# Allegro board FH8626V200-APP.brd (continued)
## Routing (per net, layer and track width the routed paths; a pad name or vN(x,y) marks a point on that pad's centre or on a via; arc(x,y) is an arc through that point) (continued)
D5.0V: length 218.3
  TOP w0.381: R10.1 119.76,48.26 v1(119.38,47.88) ; R7.1 v1(139.12,42.04) ; R91.2 v2(28.32,12.32)
  VCC w0.965: 44.09,6.4 28.63,6.4 26.16,3.94 21.59,3.94 20.32,5.21 20.32,20.32 12.83,27.81 10.41,27.81 4.57,33.66 4.57,53.95 5.54,54.91 8.97,54.91 9.96,55.91 v1(12.24,55.91) ; 44.09,6.4 57.66,6.4 60.08,8.83 80.51,8.83 84.25,5.08 91.06,5.08 92.49,3.65 94.2,3.65 95.61,5.05 103.23,5.05 108.36,10.19 119.87,10.19 122.05,12.36 122.05,28.07 ; 44.09,6.4 44.04,6.45 44.04,10.01
  VCC w1.016: 29.13,6.4 28.7,6.83 28.7,11.94 v2(28.32,12.32)
  BOTTOM w0.305: R105.1 43.81,11.05 43.99,11.23
  BOTTOM w0.381: v1(139.12,42.04) 139.24,41.91 R44.1 ; v1(121.41,33.15) 121.28,33.02 R18.1 ; R86.1 v1(121.28,29.46) ; R15.1 v1(121.18,36.2) ; R24.1 v1(118.49,45.44) ; R21.1 119.76,46.99 v1(119.38,47.37)
  vias: v1(11.68,55.88) v1(12.85,55.88) v1(43.84,11.43) v1(44.4,11.46) v1(102.49,71.5) v1(103,71.5) v1(103.5,71.5) v1(116.59,80.26) v1(117.09,80.26) v1(117.6,80.26) v1(118.87,47.88) v1(118.87,47.37) v1(121.41,32.64) v1(121.41,32.13) v1(121.41,26.54) v1(121.41,26.04) v1(121.41,25.53) v1(121.92,41.27) v1(121.92,40.77) v1(121.92,40.26) v1(121.92,33.15) v1(121.92,32.64) v1(121.92,32.13) v1(121.92,26.54) v1(121.92,26.04) v1(121.92,25.53) v1(122.43,41.27) v1(122.43,40.77) v1(122.43,40.26) v1(123.67,35) v1(123.67,34.44) v1(124.46,34.44) v1(125.17,35.1) v1(125.17,34.44) v1(128.07,42.04) v1(128.07,41.53) v1(128.07,41.02) v1(128.58,42.04) v1(128.58,41.53) v1(128.58,41.02)
D12V: length 8.4
  TOP w0.305: 133.1,23.75 v1(133.1,22.99)
  BOTTOM w0.305: R1.2 v1(133.1,13.59)
  BOTTOM w0.508: U19.1 C153.1 C152.1 v1(8.38,10.16)
  vias: v1(8.64,18.95) v1(8.66,18.41) v1(8.69,17.91) v1(9.25,18.97) v1(9.25,17.88) v1(9.27,18.44) v1(137.54,28.07) v1(140.13,28.27) v1(140.11,27.71) v1(140.13,27.18)
GND: length 2115.5
  TOP w0.102: v1(54.61,34.54) 54.61,33.48 53.37,32.23 v1(53.37,30.58) 53.37,28.42 v1(53.59,28.19) v1(53.59,25.4) ; v1(50.77,43.15) 45.16,43.15 v1(45.01,43) 44.96,42.95 v1(41.71,42.95) ; 64.49,23.77 64.52,23.75 v1(64.52,22.1) v1(64.52,21.21) 64.39,21.21 63.89,20.71 U7.2 63.46,20.4 62.87,19.81 60.71,19.81 60.2,20.32 v1(60.2,20.57) v1(60.2,21.46) v1(60.2,22.48) 60.2,23.62 v1(60.45,23.88) ; v1(60.86,31.83) 60.86,27.58 60.1,26.82 v1(60.1,24.89) ; v1(132.05,56.41) 129.44,53.8 v1(125.81,53.8) v1(121.77,53.8) v1(116.31,53.8) v1(110.67,53.8) v1(104.9,53.8) v1(101.63,53.8) 92.6,53.8 BT1.2 ; v1(54.56,35.51) 54.28,35.51 53.78,35.01 53.78,33.54 52.5,32.26 v1(52.5,31.5) v1(52.5,28.57) 52.5,25.07 v1(52.45,25.02) ; v1(52.83,48.72) 52.83,49.86 52.3,50.39 52.3,52.73 v1(51.63,53.4) 49.48,55.55 45.8,55.55 45.11,54.86 44.86,54.86 44.81,54.81 44.81,54.64 44.17,54 v1(43.66,54) v1(40.54,54) 40.46,54.08 37.85,54.08 37.67,54.25 37.67,56.57 v1(36.96,57.28) 36.96,57.43 37.19,57.66 38.25,57.66 38.48,57.43 v1(38.48,57.4) 38.48,56.06 38.73,55.8 v1(40.29,55.8) v1(44.6,55.8) 45.19,55.8 45.39,56.01 50.55,56.01 v1(50.79,55.77) v1(52.86,53.7) 53.21,53.34 v1(53.21,52.2) ; 43.99,50.72 43.99,52.83 46.15,54.99 48.77,54.99 51.05,52.7 v1(51.05,51.54) 51.05,50.44 51.7,49.8 v1(51.7,48.29) 51.7,47.38 53.44,45.64 v1(53.47,45.64) 53.47,45.62 54.15,44.94 54.39,44.94 54.53,44.8 54.53,44.6 54.51,44.58 58.06,41.02 ; v1(67.26,14.27) 62.92,14.27 v1(62.82,14.18) 62.17,14.83 v1(59.83,14.83) 58.37,14.83 v1(56.88,16.32) 54.56,18.64 v1(54.56,20.12) v1(54.56,22.91) v1(54.56,25.98) v1(54.56,28.5) v1(54.56,30.61) 54.56,32.46 v1(54.61,32.51) 54.99,32.89 55.37,32.89 55.75,32.51 55.75,31.98 56.03,31.7 v1(56.03,30.71) v1(56.03,27.74) v1(56.03,24.87) v1(56.03,23.09) v1(56.03,18.82) v1(57.18,17.68) 58.39,16.46 v1(60.81,16.46) v1(62.99,16.46) v1(66.95,16.46) 70.48,16.46 70.61,16.59 72.69,16.59 v1(73.08,16.21) v1(76.39,12.89) 76.81,12.47 79.48,12.47 v1(81.03,10.92) v1(83.4,8.55) 84.69,7.25 v1(87.02,7.25) U6.4 89.43,6.96 v1(94.08,6.96) 96.8,6.96 97.26,6.5 98.98,6.5 99.52,7.04 v1(99.52,8) 99.52,9.17 99.75,9.4 100.74,9.4 101.27,8.86 v1(101.27,7.75) 101.27,7.59 99.57,5.89 95.05,5.89 94.95,5.99 v1(91.41,5.99) v1(86.94,5.99) 84.58,5.99 v1(83.76,6.82) v1(79.77,10.81) 78.82,11.76 76.15,11.76 v1(75.18,12.73) 72.54,15.37 v1(71.7,15.37) 71.49,15.58 69.58,15.58 68.27,14.27 v1(67.26,14.27)
  TOP w0.178: v1(59.77,35.56) 59.65,35.68 U14.37
  TOP w0.254: U26.4 v1(108.75,79.33) ; v1(110.19,73.51) 110.05,73.64 U26.11 ; v1(110.87,79.38) 110.7,79.21 U26.1 ; C186.2 v1(111.63,71.88) ; C188.2 v1(124.97,71.88) ; v1(113.28,27.43) U12.2 v1(115.7,27.43)
  TOP w0.305: v1(14.22,23.5) 14.1,23.37 C87.2 ; R16.1 v1(117.47,37.59) ; T10.1 v1(100.84,44.83) ; v1(113.72,48.9) v1(113.21,48.9) v1(112.67,48.9) 111.2,48.9 111.18,48.92 111.15,48.9 C22.2 ; C65.1 v1(118.87,28.19) ; 134.37,23.75 v1(134.37,22.99) ; J3.30 v1(6.99,49.84) ; C6.2 v1(128.91,28.83) ; J3.37 v1(10.29,53.84) ; v1(64.57,48.31) 64.64,48.39 64.64,51.79 v1(65.18,52.32) v1(66.36,53.51) 68.92,56.07 69.53,56.07 70.18,56.72 v1(70.18,58.29) 70.18,59.23 69.6,59.82 v1(69.6,61.47) D24.K ; C72.1 v1(26.42,9.4) ; J3.38 v1(6.85,53.84) ; v1(106.55,32.61) 106.43,32.74 C29.2 ; v1(63.5,21.56) 63.46,21.52 U7.2 ; C78.1 v1(60.45,23.88) ; R88.1 v1(117.47,30.99) ; U27.4 v1(122.21,79.29) ; v1(132.51,40.26) v1(133.4,40.26) 133.53,40.39 v1(134.29,40.39) U2.2 136.45,40.39 ; U3.2 v1(115.95,48.9) ; J3.10 v1(6.99,39.84) ; C39.2 105.16,44.83 v1(104.9,45.09) ; J4.8 v1(40.26,61.09) ; C9.2 130.4,28.93 v1(130.3,28.83) ; v1(65.13,23.8) 65.1,23.77 64.49,23.77 C80.1 ; v1(60.78,47.83) v1(60.78,52.7) 60.78,55.52 59.56,56.74 v1(59.56,57) 59.77,57.2 59.77,59.16 60.2,59.59 v1(60.2,60.33) v1(60.2,61.44) D18.K ; C38.2 v1(106.55,45.59) ; U14.89 56.01,41.02 v1(55.75,41.27) ; v1(14.15,35.84) J3.1 ; D3.K v1(135.13,11.81) ; v1(60.2,22.48) 60.21,22.47 U7.4 ; C11.1 v1(130.23,40.01) ; C30.2 v1(104.9,33.27) ; C14.2 v1(129.34,42.47) ; C34.1 v1(120.9,43.56) ; C15.2 v1(130.86,42.52) ; v1(65.53,47.12) 65.56,47.14 v1(66.32,47.14) v1(67.16,47.14) 67.59,47.14 68.96,48.51 v1(70.48,48.51) v1(73.34,51.37) v1(75.37,53.4) v1(78.93,56.96) v1(83.38,61.4) v1(86.04,64.07) v1(87.45,65.48) 87.39,65.54 87.39,66.66 89.03,68.3 v1(89.03,71.5) D14.A ; C37.2 108.93,44.74 v1(108.97,44.7) ; v1(15.49,23.5) R104.2 ; v1(33.43,61.01) 33.56,60.88 J4.5 ; T2.1 v1(127.76,35.43) ; C35.1 v1(119.51,42.8) ; J3.18 v1(6.99,43.84) ; J3.24 v1(6.99,46.84) ; U27.11 v1(123.52,73.59) ; R9.1 v1(132.26,37.59) ; C67.2 v1(108.97,30.1) ; J3.26 v1(6.99,47.84) ; D21.K v1(63.25,61.39) v1(63.25,59.56) 63.25,59.31 63.93,58.62 v1(63.93,57.15) 63.93,56.26 63.25,55.58 63.25,55.4 62.71,54.86 v1(62.71,54.36) v1(62.71,52.96) ; v1(62,9.8) 62.53,9.27 C108.2 ; v1(62.71,52.96) v1(62.71,50.11) v1(62.71,48.92) ; v1(62.71,52.96) 63.42,52.96 64.38,53.91 v1(64.38,54.62) 65.89,56.13 v1(65.89,57.35) v1(65.89,59.84) 65.89,60.73 v1(66.55,61.39) D22.K ; J3.4 v1(6.99,36.84) ; C71.1 v1(26.54,11.43) ; C69.2 v1(104.9,30.86) ; U27.1 v1(124.17,79.33) ; C7.2 v1(127.51,29.34) ; C68.2 106.43,30.94 v1(106.55,31.06) ; 135.64,23.75 v1(135.64,22.99) ; C18.1 v1(116.71,49.66) ; J3.20 v1(6.99,44.84) ; C16.2 v1(127.94,43.05) ; 73.28,37.97 v1(73.91,37.97) ; C28.2 108.08,33.43 108.66,32.84 v1(108.66,32.54) ; v1(68.05,45.82) 68.3,45.82 69.34,46.86 v1(71.25,46.86) v1(74.04,49.66) v1(77.34,52.96) v1(81.22,56.83) v1(86.55,62.17) v1(89.31,64.92) v1(91.01,66.62) 92.2,67.82 v1(92.2,68.96) v1(92.2,69.9) v1(92.2,71.37) D13.K ; T18.1 v1(103.76,31.75) ; J3.6 v1(6.99,37.84) ; C12.1 v1(131.62,40.13) ; C40.2 v1(103.89,44.96) ; T5.1 v1(128.14,49.53) ; C17.1 v1(119.13,49.28) ; J3.12 v1(6.99,40.84) ; C26.1 v1(118.87,34.8) ; C79.1 v1(73.91,34.8) ; U9.4 v1(77.37,17.27) ; C21.2 v1(109.09,50.16) ; J21.4 v1(87.19,72.97) ; v1(120.27,28.7) C64.1 ; C25.1 v1(120.27,35.31) ; C19.2 v1(107.57,50.16) ; J3.32 v1(6.99,50.84)
  TOP w0.381: 13.54,22.61 C87.2 14.65,22.61 ; 50.16,3.09 CN1.5 ; CN1.5 51.44,4.36 ; CN1.5 51.44,1.82 ; CN1.5 52.71,3.09 ; 48.34,80.49 J4.15 ; J4.15 47.24,81.97 ; J4.15 48.34,83.46 ; J4.15 49.43,81.97 ; 79.18,17.74 U9.4 79.18,16.8 ; S1.1 127.25,12.06 ; S1.1 124.71,12.06 ; S1.1 125.98,13.34 ; S1.1 125.98,10.79 ; 25.21,10.79 C71.1 ; C71.1 25.91,11.46 ; C71.1 25.91,10.13 ; C71.1 26.61,10.79 ; J13.CG1 5.29,66.98 ; J13.CG1 3.73,65.77 ; J13.CG1 3.73,68.19 ; J13.CG1 2.17,66.98 ; 16.46,2.96 J7.CG2 ; J7.CG2 15.25,4.52 ; J7.CG2 17.67,4.52 ; J7.CG2 16.46,6.09 ; 120.06,42.16 C35.1 118.95,42.16 ; U18.16 153.8,57.91 ; U18.16 151.76,57.91 ; U18.16 152.78,58.93 ; 64.39,23.32 C80.1 ; C80.1 64.94,23.88 ; C80.1 64.39,24.43 ; J7.CG1 11.42,4.52 ; J7.CG1 10.21,2.96 ; J7.CG1 9,4.52 ; J7.CG1 10.21,6.09 ; J19.CG2 115.56,86.95 ; J19.CG2 114.36,85.38 ; J19.CG2 114.36,88.51 ; J19.CG2 113.15,86.95 ; JP6.2 4.62,79.59 ; JP6.2 2.59,79.59 ; JP6.2 3.6,80.6 ; JP6.2 3.6,78.57 ; 4.96,43.27 J3.18 3.52,43.84 ; 92.58,13.49 U6.9 ; U6.9 94.11,13.49 ; U6.9 93.34,12.73 ; 137.54,55.37 JP5.2 ; JP5.2 139.57,55.37 ; JP5.2 138.56,56.39 ; JP5.2 138.56,54.36 ; 17.63,18.8 U16.2 16.11,18.8 ; J15.CG2 6.09,10.46 ; J15.CG2 4.52,9.26 ; J15.CG2 4.52,11.67 ; J15.CG2 2.96,10.46 ; 59.63,62.1 D18.K 60.2,62.61 ; 60.2,4.68 J6.2 ; J6.2 61.21,5.7 ; J6.2 62.23,4.68 ; J6.2 61.21,3.67 ; 88.45,72.26 D14.A 89.03,72.77 ; 117.22,2.92 117.22,3.94 ; 117.22,2.92 118.24,2.92 ; 117.22,2.92 116.2,2.92 ; 73.28,34.24 C79.1 72.72,34.8 ; BT1.2 89.53,53.53 ; BT1.2 89.53,47.94 ; BT1.2 87.88,50.73 ; BT1.2 91.19,50.73 ; 119.61,34.42 C25.1 120.93,34.42 ; U18.18 152.78,56.39 ; U18.18 153.8,55.37 ; U18.18 152.78,54.36 ; U18.18 151.76,55.37 ; 126.36,35.43 T2.1 127,36.07 ; 16.11,19.75 U16.3 ; U16.3 16.87,20.23 ; U16.3 17.63,19.75 ; 129.05,2.97 J12.2 129.05,4.39 ; U18.8 152.78,69.09 ; U18.8 152.78,67.06 ; U18.8 153.8,68.07 ; JP5.1 139.57,52.83 ; JP5.1 138.56,53.85 ; JP5.1 137.54,52.83 ; JP5.1 138.56,51.82 ; U18.6 153.8,70.61 ; U18.6 152.78,69.6 ; U18.6 151.76,70.61 ; R5.1 130.81,28 ; R5.1 130.3,27.43 ; R5.1 131.32,27.43 ; 100.96,50.67 T6.1 ; T6.1 v1(102.36,50.67) ; T6.1 101.6,51.31 ; T6.1 101.6,50.04 ; J20.CG2 126.93,88.51 ; J20.CG2 128.14,86.95 ; J20.CG2 125.72,86.95 ; J20.CG2 126.93,85.38 ; 65.98,62.1 D22.K 66.55,62.61 ; 3.73,72.02 J13.CG2 ; J13.CG2 5.29,73.23 ; J13.CG2 3.73,74.44 ; J13.CG2 2.17,73.23 ; 63.25,62.61 D21.K 63.82,62.1 ; 5.46,71.29 J13.2 6.88,70.73 ; J17.13 56.99,82.61 ; J17.13 55.55,81.18 ; J17.13 56.99,79.74 ; J17.13 58.43,81.18 ; JP6.1 4.62,77.05 ; JP6.1 3.6,78.06 ; JP6.1 3.6,76.03 ; JP6.1 2.59,77.05 ; 73.25,79.74 J17.14 ; J17.14 71.81,81.18 ; J17.14 74.69,81.18 ; J17.14 73.25,82.61 ; C5.2 139.93,25.78 ; C5.2 138.97,24.89 ; C5.2 138.02,25.78 ; C4.2 142.31,25.78 ; C4.2 140.41,25.78 ; C4.2 141.36,24.89 ; 113.69,34.04 U4.2 115.52,34.04 ; U18.12 152.78,64.01 ; U18.12 153.8,62.99 ; U18.12 152.78,61.98 ; U18.12 151.76,62.99 ; J20.CG1 119.39,86.95 ; J20.CG1 118.18,85.38 ; J20.CG1 116.97,86.95 ; J20.CG1 118.18,88.51 ; 81.48,78.77 J21.CG2 ; J21.CG2 84.66,78.77 ; J21.CG2 83.07,81.48 ; J21.CG2 83.07,76.07 ; 137.16,25.73 C2.2 137.71,26.29 ; 116.15,42.16 U5.2 114.32,42.16 ; 4.52,15.51 J15.CG1 ; J15.CG1 2.96,16.71 ; J15.CG1 6.09,16.71 ; J15.CG1 4.52,17.92 ; 127,48.89 T5.1 ; T5.1 127,50.17 ; T5.1 126.36,49.53 ; 110.49,51.18 110.49,51.74 ; 110.49,51.18 111.04,51.18 ; 110.49,51.18 109.94,51.18 ; 130.2,43.31 C15.2 131.52,43.31 ; 9.33,21.15 C105.2 ; C105.2 10.29,22.04 ; C105.2 11.24,21.15 ; 130.48,37.59 R9.1 130.99,37.02 ; 153.92,11.45 C3.2 ; C3.2 154.94,12.47 ; C3.2 152.91,12.47 ; C3.2 153.92,13.49 ; 117.27,48.9 C18.1 116.16,48.9 ; 134.87,23.75 133.86,23.75 ; 116.71,38.16 R16.1 116.2,37.59 ; C23.1 v1(115.82,51.56) ; 142.62,6.89 J1.2 ; J1.2 144.53,7.84 ; J1.2 140.72,7.84 ; J1.2 142.62,8.8 ; S2.1 125.98,22.23 ; S2.1 124.71,20.95 ; S2.1 127.25,20.95 ; S2.1 125.98,19.68 ; 129.57,29.72 C6.2 128.24,29.72 ; 123.65,71.88 C188.2 124.21,71.33 ; J21.CG1 98.32,81.48 ; J21.CG1 99.91,78.77 ; J21.CG1 98.32,76.07 ; J21.CG1 96.73,78.77 ; v1(13.84,38.84) J3.7 ; T18.1 104.39,30.99 ; T18.1 103.76,30.35 ; T18.1 103.12,30.99 ; 11.56,19.81 C106.2 ; C106.2 12.06,20.32 ; C106.2 12.57,19.81 ; 11.18,85.41 J14.3 ; J14.3 12.26,86.49 ; J14.3 10.1,86.49 ; J14.3 11.18,87.57 ; U18.10 152.78,66.55 ; U18.10 152.78,64.52 ; U18.10 153.8,65.53 ; 92.77,72.26 D13.K 92.2,72.77 ; 146.47,11.34 J1.3 ; J1.3 148.37,11.34 ; J1.3 147.42,9.44 ; J1.3 147.42,13.25 ; 119.61,27.81 C64.1 120.93,27.81 ; J21.4 87.19,77.01 ; J21.4 88.02,75.31 ; J21.4 86.37,75.31 ; C28.2 108.74,33.53 ; C28.2 107.42,33.53 ; C28.2 108.08,34.23 ; 138.41,16.83 D2.A ; D2.A 137.31,18.29 ; D2.A 138.41,19.75 ; 138.36,38.94 C20.1 ; C20.1 v1(139.12,39.5) ; C20.1 138.36,40.05 ; U15.4 118.24,5.46 ; U15.4 116.2,5.46 ; U15.4 117.22,4.44 ; U15.4 117.22,6.48 ; 18.94,81.97 J4.16 ; J4.16 20.04,80.49 ; J4.16 21.13,81.97 ; J4.16 20.04,83.46 ; 130.43,40.13 C12.1 130.99,39.58 ; 120.24,42.55 C34.1 121.57,42.55 ; 105.61,85.38 J19.CG1 ; J19.CG1 106.81,86.95 ; J19.CG1 104.4,86.95 ; J19.CG1 105.61,88.51 ; v1(13.84,48.51) 13.51,48.84 J3.27 ; 58.42,37.71 U14.89 ; U14.89 61.74,41.02 ; U14.89 58.42,44.34 ; T8.1 104.27,36.83 ; T8.1 103,36.83 ; T8.1 103.63,37.47 ; 25.92,4.52 J5.CG2 ; J5.CG2 27.13,2.96 ; J5.CG2 28.33,4.52 ; J5.CG2 27.13,6.09 ; 151.51,38.6 J2.3 ; J2.3 148.08,39.99 ; J2.3 151.51,41.39 ; J2.3 154.94,39.99 ; 61.21,24.43 C78.1 61.21,23.32 ; 29.78,20.45 30.86,20.45 ; 30.86,20.45 30.86,19.37 ; 30.86,20.45 31.94,20.45 ; 30.86,20.45 30.86,21.53 ; U6.10 94.11,4.79 ; U6.10 92.58,4.79 ; U6.10 93.34,4.03 ; R8.1 138.36,41.28 ; R8.1 138.36,40.26 ; R8.1 v1(139.12,40.77) ; 110.32,71.88 C186.2 110.87,71.33 ; 129.34,39.31 C11.1 128.68,40.01 ; 151.76,60.45 U18.14 ; U18.14 152.78,59.44 ; U18.14 152.78,61.47 ; U18.14 153.8,60.45 ; 16,22.61 R104.2 14.99,22.61 ; v1(13.97,41.84) J3.13 ; J3.13 10.58,41.84 ; J3.13 12.02,42.41 ; 106.91,49.28 C19.2 108.23,49.28 ; 39.45,59.77 J4.8 41.06,59.77 ; 61.26,21.7 U7.4 61.26,23.23 ; 25.4,8.84 C72.1 25.4,9.95 ; U18.20 153.8,52.83 ; U18.20 151.76,52.83 ; U18.20 152.78,53.85 ; U18.20 152.78,51.82 ; 133.73,27.3 U1.2 131.95,27.3 ; CN5.5 35.56,4.36 ; CN5.5 34.29,3.09 ; CN5.5 35.56,1.82 ; CN5.5 36.83,3.09 ; U18.4 153.8,73.15 ; U18.4 151.76,73.15 ; U18.4 152.78,74.17 ; T10.1 101.73,45.47 ; T10.1 102.36,44.83 ; T10.1 101.73,44.2 ; C29.2 107.09,33.53 ; C29.2 105.76,33.53 ; C29.2 106.43,34.23 ; R11.1 v1(117.22,51.56) ; 136.19,23.75 135.08,23.75 ; 105.71,44.32 C39.2 104.6,44.32 ; 131.06,29.75 C9.2 129.74,29.75 ; 130,43.31 C14.2 128.68,43.31 ; 104.35,29.97 C69.2 105.46,29.97 ; v1(13.84,45.84) J3.21 ; D3.K 135.79,12.96 ; D3.K 134.47,12.96 ; D3.K 135.13,13.62 ; 20.88,2.96 J5.CG1 ; J5.CG1 22.09,4.52 ; J5.CG1 19.67,4.52 ; J5.CG1 20.88,6.09 ; 12.02,35.27 J3.1 10.58,35.84 ; 103.33,44.32 C40.2 104.44,44.32 ; 119.43,34.04 C26.1 118.32,34.04 ; 119.43,27.43 C65.1 118.32,27.43 ; 116.33,45.59 R26.1 ; R26.1 117.22,45.59 v1(117.47,45.34) ; R26.1 116.84,46.17 ; 110.49,49.45 C22.2 109.94,48.9 ; 109.75,49.28 C21.2 108.43,49.28 ; J3.33 14.86,51.84 ; 70.17,62.1 D24.K 69.6,62.61
  TOP w0.508: J13.2 v1(3.69,70.73)
  VCC w0.102: v1(65.43,27.99) 67.31,26.11 89.46,26.11 90.17,26.82 90.17,28.7 89.76,29.11 v1(89.36,29.11) ; 65.43,22.76 v1(67.36,22.76) v1(68.66,22.76) v1(71.15,22.76) v1(74.07,22.76) v1(77.19,22.76) v1(81.79,22.76) 83.08,21.46 90.6,21.46 91.9,22.76 v1(93.4,22.76) ; 65.43,22.76 v1(65.33,22.76) 64.87,22.76 61.59,26.04 54.61,26.04 v1(54.56,25.98) 54.91,25.98 v1(56.03,24.87) ; 65.43,22.76 65.43,22.48 66.19,21.72 v1(70.87,21.72) 71.02,21.87 78.61,21.87 78.69,21.79 v1(79.15,21.79) 79.15,21.46 78.54,20.85 v1(72.14,20.85) v1(67.82,20.85) 64.92,20.85 ; 33.9,55.77 27.17,55.77 v1(26.8,56.13) 26.47,56.13 26.09,55.75 24.77,55.75 22.81,57.71 v1(22.81,59.03) ; 33.9,55.77 40.25,55.77 ; 33.9,55.77 v1(33.53,56.13) ; 40.25,55.77 44.56,55.77 v1(44.6,55.8) 45.54,56.74 49.81,56.74 v1(50.79,55.77) 53.1,55.77 57.07,51.79 58.29,51.79 58.45,51.94 59.49,51.94 59.72,51.71 59.99,51.71 ; 40.25,55.77 v1(40.29,55.8) ; v1(43.66,54) 45.03,54 46.01,54.98 48.65,54.98 51.05,52.57 v1(51.05,51.54) ; v1(63.5,21.56) 64.21,20.85 64.92,20.85 ; v1(55.91,34.95) 56.72,35.76 57.15,35.76 57.28,35.89 59.44,35.89 v1(59.77,35.56) 60.05,35.84 61.14,35.84 61.2,35.78 ; 64.92,20.85 v1(64.52,20.45) 64.39,20.32 60.45,20.32 v1(60.2,20.57) 58.55,20.57 v1(56.03,23.09) 53.98,25.15 53.85,25.15 v1(53.59,25.4) 53.47,25.53 52.96,25.53 v1(52.45,25.02) 52.45,24.89 54.43,22.91 v1(54.56,22.91) 54.81,22.91 v1(56.05,21.68) 57.89,19.84 v1(57.96,19.84) 58.09,19.84 58.32,19.61 65.96,19.61 v1(66.17,19.81) v1(68.78,19.81) v1(90.5,19.81) 92.99,19.81 v1(93.34,19.46) ; v1(87.86,23.83) v1(83.59,23.83) v1(78.36,23.83) v1(73.79,23.83) v1(69.27,23.83) 65.02,23.83 61.11,27.74 v1(56.03,27.74) 55.97,27.8 55.26,27.8 v1(54.56,28.5) ; v1(80.16,20.85) 80.26,20.75 91.62,20.75 v1(91.95,21.08) 95.22,21.08 v1(96.58,19.72) 97.87,18.44 v1(100.79,18.44) ; v1(74.8,46.23) 74.4,45.82 v1(68.05,45.82) 67.74,45.82 67.59,45.97 v1(64.39,45.97) ; v1(65.71,30.1) 65.71,29.51 68.2,27.03 71.37,27.03 72.19,27.84 v1(72.72,27.84)
  VCC w0.381: C3.2 154.94,12.47 ; C3.2 153.92,13.49 ; C3.2 152.91,12.47 ; C3.2 153.92,11.45 ; 152.78,67.06 U18.8 ; U18.8 151.76,68.07 ; U18.8 152.78,69.09 ; U18.8 153.8,68.07 ; U6.10 93.34,5.56 ; U6.10 94.11,4.79 ; U6.10 92.58,4.79 ; J2.3 151.51,41.39 ; J2.3 151.51,38.6 ; J2.3 148.08,39.99 ; J2.3 154.94,39.99 ; U18.12 153.8,62.99 ; U18.12 152.78,61.98 ; U18.12 152.78,64.01 ; U18.12 151.76,62.99 ; 124.71,20.95 S2.1 ; S2.1 127.25,20.95 ; S2.1 125.98,19.68 ; S2.1 125.98,22.23 ; 151.76,65.53 U18.10 ; U18.10 152.78,66.55 ; U18.10 153.8,65.53 ; U18.10 152.78,64.52 ; 152.78,54.36 U18.18 ; U18.18 151.76,55.37 ; U18.18 153.8,55.37 ; U18.18 152.78,56.39 ; 3.6,76.03 JP6.1 ; JP6.1 3.6,78.06 ; JP6.1 4.62,77.05 ; JP6.1 2.59,77.05 ; U6.9 94.11,13.49 ; U6.9 92.58,13.49 ; U6.9 93.34,14.26 ; U6.9 93.34,12.73 ; 152.78,51.82 U18.20 ; U18.20 151.76,52.83 ; U18.20 152.78,53.85 ; U18.20 153.8,52.83 ; 152.78,72.14 U18.4 ; U18.4 151.76,73.15 ; U18.4 152.78,74.17 ; U18.4 153.8,73.15 ; 138.56,51.82 JP5.1 ; JP5.1 139.57,52.83 ; JP5.1 138.56,53.85 ; JP5.1 137.54,52.83 ; 35.56,1.82 CN5.5 ; CN5.5 36.83,3.09 ; CN5.5 34.29,3.09 ; J17.14 73.25,82.61 ; J17.14 71.81,81.18 ; J17.14 74.69,81.18 ; J17.14 73.25,79.74 ; U18.16 153.8,57.91 ; U18.16 152.78,58.93 ; U18.16 151.76,57.91 ; U18.16 152.78,56.9 ; U18.14 153.8,60.45 ; U18.14 152.78,59.44 ; U18.14 152.78,61.47 ; U18.14 151.76,60.45 ; 11.18,85.41 J14.3 ; J14.3 12.26,86.49 ; J14.3 10.1,86.49 ; J14.3 11.18,87.57 ; JP6.2 3.6,80.6 ; JP6.2 2.59,79.59 ; JP6.2 3.6,78.57 ; JP6.2 4.62,79.59 ; U18.6 153.8,70.61 ; U18.6 151.76,70.61 ; U18.6 152.78,71.63 ; U18.6 152.78,69.6 ; 29.78,20.45 30.86,20.45 ; 30.86,20.45 30.86,19.37 ; 30.86,20.45 30.86,21.53 ; 30.86,20.45 31.94,20.45 ; U6.4 89.9,7.25 ; U6.4 88.37,7.25 ; U6.4 89.13,8.02 ; U6.4 89.13,6.49 ; 50.16,3.09 CN1.5 ; CN1.5 52.71,3.09 ; CN1.5 51.44,1.82 ; 138.56,54.36 JP5.2 139.57,55.37 ; J1.3 148.37,11.34 ; J1.3 147.42,9.44 ; J1.3 147.42,13.25 ; J1.3 146.47,11.34 ; 55.55,81.18 J17.13 ; J17.13 56.99,82.61 ; J17.13 58.43,81.18 ; J17.13 56.99,79.74 ; 116.2,5.46 U15.4 118.24,5.46 ; 117.22,2.92 118.24,2.92 ; 117.22,2.92 117.22,1.9 ; 117.22,2.92 116.2,2.92 ; 61.21,3.67 J6.2 62.23,4.68 ; S1.1 127.25,12.06 ; S1.1 125.98,13.34 ; S1.1 124.71,12.06 ; J1.2 144.53,7.84 ; J1.2 142.62,6.89 ; J1.2 142.62,8.8 ; J1.2 140.72,7.84
  BOTTOM w0.102: 36.91,41.66 v1(36.4,41.15) v1(33.81,38.56) 31.13,35.88 v1(30.76,35.88) v1(25.17,35.88) v1(21.51,35.88) 21.48,35.84 v1(14.15,35.84) 14.08,35.84 v1(8.26,41.66) 7.65,42.27 7.25,42.27 6.99,42.01 v1(6.99,40.84) v1(9.63,38.2) 13.25,34.57 v1(14.38,34.57) v1(18.62,34.57) v1(20.93,34.57) v1(23.34,34.57) v1(27.61,34.57) 32.08,34.57 v1(32.28,34.77) v1(36.39,38.87) 38.02,40.51 v1(43,40.51) 43.13,40.64 v1(46.63,40.64) ; 36.91,41.66 v1(38.2,42.95) v1(39.83,44.58) v1(41.66,44.58) ; 36.91,41.66 v1(40.41,41.66) 41.66,41.66 ; v1(50.04,36.7) 49.91,36.7 49.53,36.32 48.64,36.32 48.26,35.94 48.26,35.81 48.13,35.69 46.23,35.69 45.85,35.31 v1(45.72,35.31) 45.72,35.18 42.42,31.88 v1(42.42,30.23) 42.42,26.16 v1(43.81,24.77) v1(46.67,21.91) v1(48.77,19.81) v1(51.56,17.02) 52.37,16.21 52.37,15.85 52.49,15.74 52.72,15.74 52.96,15.49 v1(54.74,15.49) ; 40.64,26.16 v1(40.64,28.32) 40.64,32.26 v1(40.77,32.38) 40.77,32.64 v1(42.93,34.8) 45.21,37.08 v1(47.24,37.08) ; 40.64,26.16 v1(44.26,22.54) v1(47.31,19.49) v1(49.66,17.14) v1(51.31,15.49) ; 40.64,26.16 v1(40.64,22.48) v1(40.64,20.07) 37.72,17.14 v1(37.72,14.73) ; 41.66,41.66 41.66,42.9 v1(41.71,42.95) 41.66,43 v1(41.66,44.58) ; 41.66,41.66 v1(45.97,41.66) ; v1(6.85,53.84) 8.13,53.84 13.46,48.51 v1(13.84,48.51) v1(16.64,48.51) v1(24.51,48.51) v1(31.67,48.51) v1(39.12,48.51) 42.04,48.51 v1(45.97,44.58) ; v1(51.7,48.29) 51.42,48.01 48.74,48.01 v1(48.46,48.29) ; v1(48.13,34.54) 47.24,34.54 v1(45.85,33.15) 43.94,31.24 v1(43.94,30.1) 43.94,27.51 v1(43.94,27.51) 43.94,27.06 v1(46.23,24.77) v1(48.77,22.23) v1(51.05,19.94) v1(52.83,18.16) 56.64,18.16 57.78,17.02 v1(57.78,13.34) ; v1(41.66,44.58) v1(41.66,45.97) 41.66,46.7 41.01,47.35 39.17,47.35 39.12,47.29 ; v1(19.79,38.89) 13.89,38.89 v1(13.84,38.84) ; 25.45,38.89 v1(26.87,38.89) v1(30.94,38.89) 31.57,38.89 v1(34.51,41.82) v1(37.36,44.68) v1(38.79,46.1) 39.12,46.43 v1(39.12,46.86) 39.12,47.29 ; 39.12,47.29 38.96,47.14 v1(37.26,47.14) 36.86,47.14 36.41,46.7 v1(34.71,46.7) v1(31.37,46.7) v1(28.38,46.7) v1(23.77,46.7) 16.76,46.7 v1(15.9,45.84) v1(13.84,45.84) ; v1(10.29,53.84) 14.6,49.53 v1(15.49,49.53) v1(22.61,49.53) v1(29.84,49.53) v1(38.1,49.53) 42.16,49.53 45.85,45.85 48.51,45.85 C52.1 ; 48.01,37.08 C55.2 48.01,37.47 48.39,37.85 49.82,37.85 50.29,38.33 50.29,38.86 50.04,39.12 v1(49.91,39.12) 49.89,39.09 49.63,39.09 49.53,38.99 47.37,38.99 v1(46.74,38.35) 44.32,38.35 v1(43.75,37.78) v1(41.78,35.81) v1(40.13,34.16) 38.18,32.21 v1(38.18,28.96) v1(38.18,24.74) v1(38.18,21.97) 38.18,20.65 35.81,18.29 34.77,18.29 v1(33.76,17.27) ; v1(21.21,41.22) v1(18.06,41.22) v1(15.54,41.22) 14.66,41.22 14.3,41.58 14.23,41.58 v1(13.97,41.84)
  BOTTOM w0.178: R31.2 v1(64.39,45.97) ; C57.2 55.93,34.42 v1(55.91,34.44)
  BOTTOM w0.201: C75.2 C74.2 51.31,40.01 50.84,40.48 v1(50.52,40.48)
  BOTTOM w0.305: C163.2 v1(115.32,21.59) ; C161.2 v1(107.19,14.22) ; C52.1 49.38,45.34 49.68,45.03 v1(49.68,44.75) ; C158.2 v1(98.17,72.77) ; R46.2 v1(26.8,56.13) ; Q1.2 v1(47.17,70) ; C100.1 67.18,12.32 v1(66.8,12.7) ; v1(68.07,42.8) 67.94,42.67 C49.2 C51.2 65.66,42.67 v1(65.53,42.8) ; R87.1 114.96,29.46 v1(114.83,29.34) ; C102.2 v1(79.76,34.04) ; v1(99.82,72.39) 99.69,72.52 C159.2 ; C195.1 v1(123.83,4.83) ; C62.2 v1(140.51,43.18) R84.2 ; C147.2 v1(30.73,13.59) ; v1(114.68,20.22) 115.09,19.81 C164.2 ; C116.2 C117.2 56.21,36.62 56.21,37.33 56.21,37.34 v1(56.21,37.36) ; R43.2 v1(18.16,57.02) ; C44.2 50.55,44.96 50.34,44.75 v1(50.19,44.75) ; C135.2 v1(48.13,34.54) ; v1(110.36,18.03) 110.24,18.16 C162.2 ; v1(53.21,52.2) 53.34,52.2 53.47,52.07 C178.2 ; R142.2 v1(145.16,55.37) ; C107.1 v1(41.78,12.45) R106.1 ; v1(60.96,33.27) 60.71,33.53 C121.2 ; v1(59.94,62.87) 60.71,63.63 C165.2 ; v1(55.12,44.7) 56.26,45.85 57.28,45.85 ; RF2.1 v1(34.42,12.95) ; v1(35.26,62.38) 35.53,62.1 C103.2 ; C124.2 v1(59.18,48.9) C125.2 ; C177.2 56.01,30.73 v1(56.03,30.71) ; R48.2 v1(33.53,56.13) ; C167.2 69.09,63.63 v1(69.85,62.87) ; 59.31,77.34 v1(59.94,77.34) ; C43.2 C42.2 66.17,46.99 v1(66.32,47.14) ; C43.2 67.31,46.99 v1(67.16,47.14) ; C43.2 67.89,45.97 v1(68.05,45.82) ; 61.85,77.34 v1(61.85,78.36) ; C119.2 v1(45.72,9.91) ; v1(56.52,42.74) 56.45,42.67 55.12,42.67 ; Q3.2 v1(7.29,75.24) ; v1(60.91,34.32) 60.81,34.42 C120.2 ; C45.1 62.61,34.01 v1(63.07,34.47) 62.61,34.92 C50.1 ; D19.A v1(73.79,77.34) ; v1(60.13,32.91) 60.11,32.93 59.93,32.93 59.88,32.98 58.97,32.98 58.66,33.29 C98.2 C58.2 ; C148.2 v1(131.19,5.84) D8.K ; R80.2 v1(46.86,70.74) ; U10.4 v1(77.57,13.46) ; C122.2 62.48,48.69 v1(62.71,48.92) ; D10.A v1(128.65,4.57) ; C194.2 v1(123.83,3.43) ; v1(113.31,34.37) v1(113.31,33.81) 114.05,33.07 C32.2 ; 47.88,40.51 v1(49.78,40.51) ; C114.2 v1(49.58,34.54) ; v1(62.71,50.11) 62.48,49.89 C123.2 ; v1(42.55,14.61) U11.2 v1(42.55,17.02) v1(42.55,17.78) v1(42.55,18.67) ; 48.01,37.08 v1(47.24,37.08) ; Q4.2 v1(102.44,69.27) ; C113.2 v1(54.86,16.26) ; R139.2 v1(145.03,62.99) ; C60.2 v1(103.38,10.54) ; C160.2 v1(111.12,14.22) ; R176.1 v1(67.94,77.34) ; C70.1 v1(113.51,29.46) ; R173.1 v1(113.54,14.22) ; D9.A v1(125.35,4.57)
  BOTTOM w0.381: 93.34,4.03 U6.10 ; U6.10 93.34,5.56 ; U6.10 94.11,4.79 ; U6.10 92.58,4.79 ; C184.1 110.49,74.85 ; C184.1 111.04,74.3 ; C184.1 110.49,73.74 ; 152.78,72.14 U18.4 ; U18.4 153.8,73.15 ; U18.4 151.76,73.15 ; U18.4 152.78,74.17 ; J2.3 151.51,41.39 ; J2.3 154.94,39.99 ; J2.3 148.08,39.99 ; J2.3 151.51,38.6 ; 152.78,59.44 U18.14 ; U18.14 151.76,60.45 ; U18.14 153.8,60.45 ; U18.14 152.78,61.47 ; 25.65,56.13 R46.2 26.16,56.71 ; 41.15,12.95 R106.1 41.15,11.94 ; 145.8,75.61 C150.1 145.24,75.06 ; 152.78,69.6 U18.6 ; U18.6 153.8,70.61 ; U18.6 151.76,70.61 ; U18.6 152.78,71.63 ; 57.78,45.85 57.28,45.85 57.28,45.34 ; JP6.2 4.62,79.59 ; JP6.2 3.6,80.6 ; JP6.2 3.6,78.57 ; JP6.2 2.59,79.59 ; 114.68,33.02 R19.2 ; R19.2 115.19,33.59 ; R19.2 115.7,33.02 ; v1(55.9,33.4) 55.9,33.4 C48.2 ; D25.A 27.6,5.84 ; D25.A 26.18,5.84 ; D25.A v1(26.89,6.82) ; D25.A 26.89,5.1 ; 47.83,69.22 Q1.2 46.51,69.22 ; J1.3 147.42,13.25 ; J1.3 148.37,11.34 ; J1.3 146.47,11.34 ; J1.3 147.42,9.44 ; 141.78,43.18 R84.2 141.28,42.61 ; U10.9 77.38,15.37 ; U10.9 75.43,12.95 ; U10.9 75.43,17.78 ; 46.74,16.13 46.74,16.83 ; 46.74,16.13 46.07,16.13 ; 46.74,16.13 46.74,15.43 ; 46.74,16.13 47.4,16.13 ; 88.37,7.25 U6.4 ; U6.4 89.13,6.49 ; U6.4 89.9,7.25 ; U6.4 89.13,8.02 ; D16.A 73.81,72.71 ; D16.A 73.81,69.79 ; D16.A 74.91,71.25 ; 114.05,14.99 R173.1 113.03,14.99 ; 114.93,36.2 R17.1 ; R17.1 115.44,36.77 ; R17.1 115.95,36.2 ; v1(51.69,37.21) 51.56,37.08 C63.1 ; CN1.5 51.44,4.36 ; CN1.5 51.44,1.82 ; CN1.5 52.71,3.09 ; CN1.5 50.16,3.09 ; J17.13 56.99,82.61 ; J17.13 58.43,81.18 ; J17.13 55.55,81.18 ; J17.13 56.99,79.74 ; 68.71,77.85 R176.1 68.71,76.83 ; U18.18 152.78,56.39 ; U18.18 152.78,54.36 ; U18.18 153.8,55.37 ; U18.18 151.76,55.37 ; J6.2 61.21,5.7 ; J6.2 62.23,4.68 ; J6.2 61.21,3.67 ; J6.2 60.2,4.68 ; 152.78,64.52 U18.10 ; U18.10 152.78,66.55 ; U18.10 153.8,65.53 ; U18.10 151.76,65.53 ; 131.75,5.21 C148.2 131.19,4.65 ; 125.98,19.68 S2.1 ; S2.1 127.25,20.95 ; S2.1 125.98,22.23 ; S2.1 124.71,20.95 ; C91.2 60.96,39.67 ; C91.2 60.52,39.12 v1(60.33,38.93) ; C91.2 61.51,39.12 ; 22.59,9.35 U13.7 ; U13.7 23.11,10.5 ; U13.7 23.64,9.35 ; C83.1 55.67,37.34 ; C83.1 55.12,36.78 ; C83.1 55.12,37.89 ; 46.35,71.5 R80.2 47.37,71.5 ; 61.47,45.72 R49.2 ; R49.2 61.47,46.74 ; R49.2 62.81,46.23 v1(63.37,46.79) ; 113.49,33.02 C32.2 114.6,33.02 ; 124.71,12.06 S1.1 ; S1.1 127.25,12.06 ; S1.1 125.98,13.34 ; S1.1 125.98,10.79 ; 152.78,61.98 U18.12 ; U18.12 151.76,62.99 ; U18.12 152.78,64.01 ; U18.12 153.8,62.99 ; C31.1 114.17,36.75 ; C31.1 114.73,36.2 ; C31.1 113.62,36.2 ; U18.8 152.78,69.09 ; U18.8 151.76,68.07 ; U18.8 153.8,68.07 ; U18.8 152.78,67.06 ; 114.73,29.46 C70.1 114.17,30.02 ; C183.1 124.51,74.3 ; C183.1 123.95,73.74 ; C183.1 123.95,74.85 ; 111,72.11 C185.1 ; C185.1 111,73.43 ; C185.1 110.3,72.77 ; C185.1 111.7,72.77 ; 25.4,17.83 C59.1 25.95,17.27 ; 45.72,11.22 C119.2 45.17,10.67 ; 48.9,33.99 C135.2 49.45,34.54 ; U6.9 94.11,13.49 ; U6.9 92.58,13.49 ; U6.9 93.34,14.26 ; U6.9 93.34,12.73 ; 129.22,5.21 D10.A 128.65,5.72 ; C149.2 13.72,69.64 ; C149.2 14.27,69.09 ; C149.2 v1(13.72,68.45) ; 56.12,69.79 D15.A ; D15.A 55.01,71.25 ; D15.A 56.12,72.71 ; C107.1 43.24,12.45 ; C107.1 42.55,13.11 ; C107.1 42.55,11.78 ; 116.2,5.46 U15.4 ; U15.4 118.24,5.46 ; U15.4 117.22,4.44 ; U15.4 117.22,6.48 ; C166.1 66.08,75.69 ; C166.1 63.97,75.69 ; C166.1 65.02,74.74 ; C166.1 65.02,76.65 ; C41.1 115.24,44.2 ; C41.1 v1(113.67,44.2) ; C41.1 114.68,44.75 ; R25.1 115.95,44.93 v1(116.2,45.19) ; 42.93,19.51 C115.2 ; C115.2 43.48,20.07 ; C115.2 42.93,20.62 ; 59.31,76.83 59.31,77.85 ; 30.07,12.7 C147.2 ; C147.2 30.73,12 ; C147.2 31.4,12.7 ; 63.04,49.53 C123.2 62.48,48.98 ; U19.7 7.67,20.85 ; U19.7 7.11,19.52 ; U19.7 6.55,20.85 ; 35.56,1.82 CN5.5 ; CN5.5 36.83,3.09 ; CN5.5 34.29,3.09 ; CN5.5 35.56,4.36 ; C104.2 v1(41.91,65.79) ; C104.2 42.46,65.02 ; C104.2 41.36,65.02 ; J17.14 73.25,82.61 ; J17.14 73.25,79.74 ; J17.14 71.81,81.18 ; J17.14 74.69,81.18 ; 5.28,15.72 U19.3 ; U19.3 6.4,15.72 ; U19.3 5.84,14.39 ; 114.76,20.95 C163.2 115.32,20.4 ; RR2.1 v1(59.56,38.93) ; 41.15,13.29 C118.1 41.7,13.84 ; 103.93,11.18 C60.2 103.38,11.73 ; 115.95,29.46 R87.1 115.44,30.04 ; JP5.2 138.56,56.39 ; JP5.2 138.56,54.36 ; JP5.2 139.57,55.37 ; JP5.2 137.54,55.37 ; U22.1 v1(113.6,18.4) 113.59,18.42 ; 131.19,6.99 D8.K 131.76,6.48 ; 63.17,35.05 C50.1 62.61,35.61 ; v1(57.28,42.74) 57.02,42.99 C90.2 C93.2 ; 56.47,38.35 C191.2 ; C191.2 57.58,38.35 ; C191.2 57.02,38.67 v1(57.28,38.93) ; U18.20 152.78,53.85 ; U18.20 152.78,51.82 ; U18.20 153.8,52.83 ; U18.20 151.76,52.83 ; 48.13,16.08 C112.2 ; C112.2 48.69,16.64 ; C112.2 47.58,16.64 ; 151.76,57.91 U18.16 ; U18.16 152.78,58.93 ; U18.16 153.8,57.91 ; U18.16 152.78,56.9 ; C181.1 124.33,73.31 ; C181.1 125.03,72.64 ; C181.1 123.63,72.64 ; C181.1 124.33,71.98 ; 62.61,36.88 C46.1 62.61,35.77 ; 58.25,43.43 C61.2 ; C61.2 59.36,43.43 ; C61.2 58.8,42.88 ; 79.43,13 U10.4 79.43,13.92 ; R132.1 14.29,70.74 ; R132.1 13.72,71.25 ; R132.1 v1(13.72,70.1) ; 122.81,3.98 C194.2 122.81,2.87 ; 64.9,33.66 v1(64.9,33.02) ; 64.9,35.81 65.28,35.81 v1(65.53,35.56) ; Q3.2 6.47,75.9 ; Q3.2 6.47,74.57 ; Q3.2 5.71,75.24 ; 67.52,63.63 C167.2 68.07,63.07 ; 64.39,44.83 R31.2 64.96,45.34 ; C109.1 42.55,14.4 ; C109.1 42.55,13.29 ; C109.1 41.99,13.84 ; 8,72.26 8,71.25 ; C3.2 153.92,13.49 ; C3.2 152.91,12.47 ; C3.2 153.92,11.45 ; C3.2 154.94,12.47 ; C152.2 6.48,12.26 ; C152.2 5.59,11.3 ; C152.2 6.48,10.35 ; 110.79,18.8 C162.2 109.68,18.8 ; C97.2 R38.1 v1(53.47,45.64) ; R74.1 44.07,65.02 ; R74.1 v1(43.56,65.72) ; R74.1 43.05,65.02 ; 129.05,4.39 J12.2 129.05,2.97 ; 36.5,62.1 C103.2 35.94,62.66 ; JP6.1 3.6,78.06 ; JP6.1 4.62,77.05 ; JP6.1 2.59,77.05 ; JP6.1 3.6,76.03 ; 6.81,13.21 C153.2 ; C153.2 7.37,12.65 ; C153.2 7.37,13.76 ; 34.67,56.13 R48.2 34.16,56.71 ; 52.96,40.56 C75.2 53.51,40.01 ; 19.9,5.84 D7.K ; D7.K 21.32,5.84 ; D7.K 20.61,6.26 v1(21.21,6.86) ; D7.K 20.61,5.1 ; 62.61,33.35 C45.1 63.17,33.91 ; C85.1 v1(61.87,38.86) ; C85.1 62.74,39.42 ; C85.1 62.74,38.31 ; 145.8,63.5 R139.2 145.8,62.48 ; C151.2 145.8,76.75 ; C151.2 145.24,76.2 ; C151.2 145.8,75.65 ; C89.2 C88.2 56.2,39.24 v1(56.52,38.93) ; C89.2 56.26,40.39 ; C89.2 55.75,40.89 ; 55.38,43.43 C93.2 ; C93.2 55.88,42.93 ; v1(67.54,17.35) 67.59,17.4 C101.2 ; 53.97,51.56 C178.2 52.96,51.56 ; 55.24,30.18 C177.2 54.69,30.73 ; 107.74,14.99 C161.2 106.63,14.99 ; 79.12,34.59 C102.2 79.12,33.48 ; 122.81,5.38 C195.1 122.81,4.27 ; C33.2 114.02,47.04 ; C33.2 112.91,47.04 ; C33.2 v1(113.46,47.7) ; 60.96,40.34 C92.2 ; C92.2 60.77,40.89 v1(60.33,40.45) ; C92.2 60.96,41.45 ; 29.78,20.45 30.86,20.45 ; 30.86,20.45 30.86,19.37 ; 30.86,20.45 31.94,20.45 ; 89.05,75.56 D17.A ; D17.A 90.15,74.1 ; D17.A 90.15,77.03 ; RR3.1 58.55,38.67 v1(58.8,38.93) ; 137.54,52.83 JP5.1 ; JP5.1 138.56,51.82 ; JP5.1 139.57,52.83 ; JP5.1 138.56,53.85 ; Q4.2 104.01,69.27 ; Q4.2 103.25,69.93 ; Q4.2 103.25,68.61 ; J1.2 144.53,7.84 ; J1.2 142.62,8.8 ; J1.2 140.72,7.84 ; J1.2 142.62,6.89 ; 45.21,15.43 45.21,16.13 ; 45.21,16.13 44.55,16.13 ; 45.21,16.13 45.21,16.83 ; 45.21,16.13 45.87,16.13 ; 73.03,76.83 D19.A 73.03,77.85 ; 62.48,47.71 C122.2 63.04,48.26 ; 11.18,85.41 J14.3 ; J14.3 11.18,87.57 ; J14.3 10.1,86.49 ; J14.3 12.26,86.49 ; 23.75,10.93 U13.9 ; U13.9 21.79,12.45 ; U13.9 25.71,12.45 ; 63.37,43.51 C196.1 ; C196.1 63.37,44.62 ; C196.1 62.82,44.07 ; 125.35,5.72 D9.A 124.78,5.21 ; R22.2 v1(114.1,47.04) ; R22.2 114.71,47.61 ; R22.2 115.21,47.04 ; 17.65,56.13 R43.2 18.67,56.13 ; 34.93,12.19 RF2.1 33.91,12.19 ; 97.62,73.53 C158.2 98.73,73.53 ; C47.1 51.56,35.56 v1(51.94,35.94) ; 116.2,2.92 117.22,2.92 ; 117.22,2.92 117.22,3.94 ; 117.22,2.92 118.24,2.92 ; 117.22,2.92 117.22,1.9 ; 61.72,63.07 C165.2 62.28,63.63 ; 99.03,73.28 C159.2 100.36,73.28
  BOTTOM w0.508: v1(6.35,17.4) 5.84,16.89 U19.3 ; 8,71.75 v1(8.76,71.75) ; U13.7 v1(23.11,8.13) ; U19.7 v1(7.11,22.61)
  vias: v1(1.02,82.04) v1(1.02,79.5) v1(1.02,76.96) v1(1.02,74.42) v1(1.02,71.88) v1(1.02,69.34) v1(1.02,66.8) v1(1.02,64.26) v1(1.02,61.72) v1(1.02,59.18) v1(1.02,56.64) v1(1.02,54.1) v1(1.02,51.56) v1(1.02,49.02) v1(1.02,46.48) v1(1.02,43.94) v1(1.02,41.4) v1(1.02,38.86) v1(1.02,36.32) v1(1.02,33.78) v1(1.02,31.24) v1(1.02,28.7) v1(1.02,26.16) v1(1.02,23.62) v1(1.02,21.08) v1(1.02,18.54) v1(1.02,16) v1(1.02,10.92) v1(1.02,8.38) v1(2.77,75.39) v1(3.56,11.94) v1(3.56,8.89) v1(4.34,62.23) v1(4.45,11.94) v1(4.45,8.89) v1(4.62,75.51) v1(4.67,81.46) v1(4.7,32.13) v1(5.33,11.94) v1(5.33,8.89) v1(5.46,42.9) v1(5.98,26.08) v1(6.6,13.08) v1(6.6,12.45) v1(6.78,80.98) v1(6.78,66.04) v1(6.86,82.65) v1(6.86,10.16) v1(6.86,9.4) v1(7.11,4.95) v1(7.24,1.02) v1(7.49,88.77) v1(7.62,14.1) v1(8.64,42.49) v1(8.64,36.8) v1(8.76,6.6) v1(9.47,67.89) v1(9.73,62.31) v1(9.77,22.03) v1(9.78,2.79) v1(9.78,1.02) v1(10.03,88.77) v1(10.31,57.51) v1(10.52,80.54) v1(10.52,72.87) v1(10.67,2.79) v1(10.85,83.26) v1(11.05,11.43) v1(11.18,9.53) v1(11.53,77.47) v1(11.53,20.8) v1(11.76,31.65) v1(12.32,1.02) v1(12.42,21.69) v1(12.42,20.8) v1(12.57,88.77) v1(12.57,24.38) v1(12.7,83.39) v1(12.78,74.6) v1(12.92,26.2) v1(12.98,64.08) v1(13.64,60.43) v1(14.3,82.14) v1(14.33,73.66) v1(14.48,20.83) v1(14.86,43.21) v1(14.86,1.02) v1(14.99,16.33) v1(14.99,15.75) v1(14.99,14.61) v1(15.11,88.77) v1(15.11,20.19) v1(15.24,36.07) v1(15.32,55.8) v1(15.29,38.15) v1(15.47,83.82) v1(15.62,20.83) v1(15.88,20.19) v1(16,7.49) v1(16.13,72.03) v1(16.46,50.7) v1(16.84,82.02) v1(16.89,20.83) v1(17.3,54.25) v1(17.45,59.05) v1(17.4,1.02) v1(17.65,88.77) v1(17.65,21.34) v1(17.65,7.49) v1(18.03,43.56) v1(18.03,39.65) v1(18.03,20.45) v1(18.03,19.68) v1(18.34,79.4) v1(18.41,45.21) v1(18.36,38.07) v1(18.47,36.63) v1(18.54,31.83) v1(18.54,5.59) v1(18.54,3.68) v1(18.67,11.56) v1(18.67,9.65) v1(18.8,84.58) v1(18.8,20.45) v1(18.8,19.68) v1(19.33,75.95) v1(19.76,67.46) v1(19.94,1.02) v1(20.19,88.77) v1(20.22,56.34) v1(20.6,27.89) v1(20.57,24.26) v1(20.65,86.21) v1(20.83,46.1) v1(20.83,42.8) v1(21.01,61.21) v1(21.34,18.03) v1(21.59,22.35) v1(21.59,21.21) v1(22.12,79.53) v1(22.12,71.83) v1(22.25,54.53) v1(22.35,13.46) v1(22.35,12.7) v1(22.35,11.94) v1(22.48,1.02) v1(22.63,38.89) v1(22.73,88.77) v1(23.11,76.07) v1(23.24,13.46) v1(23.24,12.7) v1(23.24,11.94) v1(23.55,67.59) v1(23.65,41.78) v1(23.75,31.83) v1(23.93,61.85) v1(23.88,20.95) v1(24,22.35) v1(24.13,18.29) v1(24.13,13.46) v1(24.43,86.33) v1(24.46,83.34) v1(25.02,1.02) v1(25.15,13.46) v1(25.27,88.77) v1(26.21,64.59) v1(26.44,18.52) v1(26.57,41.86) v1(26.9,79.58) v1(26.9,71.88) v1(27.18,8.89) v1(27.56,1.02) v1(27.81,88.77) v1(27.79,57.81) v1(27.89,76.12) v1(27.94,20.83) v1(28.24,83.46) v1(28.24,31.83) v1(28.32,67.64) v1(28.45,22.35) v1(28.6,27.89) v1(28.83,15.62) v1(29.21,86.39) v1(29.16,42.44) v1(29.34,17.78) v1(30.35,88.77) v1(31.06,43.54) v1(31.95,65.25) v1(32.33,79.55) v1(32.33,71.86) v1(32.64,1.02) v1(32.89,88.77) v1(33.02,83.52) v1(33.1,43.54) v1(33.15,23.75) v1(33.32,76.1) v1(33.27,31.9) v1(33.66,22.43) v1(34.65,86.36) v1(34.67,27.36) v1(34.92,65.28) v1(35.2,68.61) v1(35.18,1.02) v1(35.43,88.77) v1(36.35,79.55) v1(36.35,71.86) v1(36.7,14.22) v1(36.7,13.34) v1(37.11,61.06) v1(37.34,76.1) v1(37.72,1.02) v1(37.97,88.77) v1(38.46,83.49) v1(38.66,86.36) v1(38.89,61.11) v1(39.24,64.49) v1(40.51,88.77) v1(40.64,62.87) v1(40.64,18.54) v1(40.64,17.02) v1(40.64,15.75) v1(40.89,69.22) v1(41.22,61.21) v1(41.66,17.02) v1(41.78,79.53) v1(41.78,71.83) v1(41.78,13.84) v1(42.16,9.78) v1(42.47,83.49) v1(42.67,57.86) v1(42.77,76.07) v1(42.85,62.94) v1(43.05,88.77) v1(43.18,12.95) v1(43.43,17.02) v1(43.61,51.94) v1(43.69,19.94) v1(43.87,1.17) v1(44.09,86.33) v1(44.32,17.02) v1(44.58,62.99) v1(44.65,65.79) v1(44.7,14.86) v1(44.91,68.05) v1(45.09,18.92) v1(45.16,9.6) v1(45.59,88.77) v1(45.85,14.86) v1(45.95,59.69) v1(45.97,12.06) v1(46.13,81.46) v1(46.48,18.92) v1(46.99,14.86) v1(47.27,78.49) v1(47.4,12.85) v1(47.55,76.07) v1(47.93,10.52) v1(48.13,88.77) v1(48.13,15.37) v1(48.64,13.84) v1(49.38,69.98) v1(49.38,0.99) v1(49.91,66.85) v1(49.99,12.22) v1(50.24,86.13) v1(50.16,45.97) v1(50.47,83.13) v1(50.67,88.77) v1(51.44,64.01) v1(52.45,33.78) v1(52.73,10.39) v1(53.06,69.95) v1(53.21,88.77) v1(53.85,66.17) v1(54.08,1.04) v1(54.23,71.25) v1(54.25,86.13) v1(54.43,59.51) v1(54.48,83.13) v1(54.86,41.91) v1(54.86,41.27) v1(55.14,57.15) v1(55.5,12.45) v1(55.63,79.51) v1(55.61,78.19) v1(55.63,42.04) v1(55.75,88.77) v1(55.93,64.85) v1(55.89,33.94) v1(55.96,76.76) v1(56.34,31.42) v1(56.52,41.97) v1(56.52,41.21) v1(56.52,40.45) v1(56.52,39.69) v1(56.95,68.43) v1(57.28,41.97) v1(57.28,41.21) v1(57.28,40.45) v1(57.28,39.69) v1(58.04,57.15) v1(58.04,42.74) v1(58.04,41.97) v1(58.04,41.21) v1(58.04,40.45) v1(58.04,39.69) v1(58.04,38.93) v1(58.29,88.77) v1(58.8,42.74) v1(58.8,41.97) v1(58.8,41.21) v1(58.8,40.45) v1(58.8,39.69) v1(58.85,59.99) v1(59.21,64.49) v1(59.39,79.71) v1(59.44,11.51) v1(59.46,78.32) v1(59.56,42.74) v1(59.56,41.97) v1(59.56,41.21) v1(59.56,40.45) v1(59.56,39.69) v1(60.33,42.74) v1(60.33,41.97) v1(60.33,41.21) v1(60.33,39.69) v1(60.83,88.77) v1(61.67,1.24) v1(62.56,31.72) v1(62.74,33.15) v1(62.74,30.48) v1(62.87,11.94) v1(63.22,83.82) v1(63.25,76.2) v1(63.27,86.23) v1(63.37,88.77) v1(63.37,74.55) v1(63.42,36.53) v1(63.63,77.47) v1(64.14,29.34) v1(64.49,31.5) v1(64.67,60.88) v1(65.02,62.33) v1(65.15,37.2) v1(65.91,88.77) v1(65.89,39.98) v1(66.37,10.67) v1(66.55,75.18) v1(66.52,4.9) v1(66.67,78.11) v1(66.67,74.17) v1(66.67,1.27) v1(67.23,83.82) v1(67.21,37.21) v1(67.18,35.7) v1(67.28,86.23) v1(67.28,39.95) v1(68.07,34.09) v1(68.33,76.2) v1(68.45,88.77) v1(68.96,42.8) v1(69.09,39.9) v1(69.47,78.49) v1(69.98,37.21) v1(70,35.67) v1(70.05,42.77) v1(70.31,4.72) v1(70.38,10.67) v1(70.99,88.77) v1(71.25,79.12) v1(71.6,59.54) v1(71.55,56.9) v1(72.03,37.21) v1(71.96,35.62) v1(72.14,32.82) v1(72.42,73.66) v1(72.36,1.19) v1(72.85,64.92) v1(73,67.72) v1(73.41,4.57) v1(73.53,88.77) v1(73.86,62.26) v1(74.3,16.95) v1(74.32,16.32) v1(74.37,30.56) v1(74.55,27.58) v1(74.68,34.98) v1(74.9,39.17) v1(74.88,32.77) v1(75.06,16.95) v1(75.08,16.32) v1(75.08,15.56) v1(75.34,37.9) v1(75.82,74.3) v1(75.77,28.22) v1(75.82,16.95) v1(75.84,16.32) v1(75.84,15.56) v1(75.84,14.8) v1(76,58.32) v1(76.1,30.73) v1(76.2,71.25) v1(76.38,35.92) v1(76.45,36.96) v1(76.63,39.09) v1(76.58,16.19) v1(76.58,15.43) v1(76.58,14.67) v1(76.71,64.19) v1(76.71,37.93) v1(76.76,35.05) v1(76.83,32.72) v1(76.89,19.86) v1(77.09,48.64) v1(77.22,30.23) v1(77.34,31.37) v1(77.75,35.95) v1(77.83,37) v1(78.23,81.2) v1(78.18,37.91) v1(78.26,39.17) v1(78.36,43.05) v1(78.46,74.07) v1(78.84,69.62) v1(78.97,35.15) v1(79.22,35.93) v1(79.3,36.97) v1(79.5,50.8) v1(79.58,37.87) v1(79.88,59.56) v1(80.16,29.82) v1(80.8,35.08) v1(80.95,65.25) v1(80.95,37.91) v1(81.03,29.79) v1(81.08,39.14) v1(82.13,37.74) v1(82.17,68.07) v1(82.3,71.25) v1(82.27,36.69) v1(82.37,35.31) v1(82.55,74.8) v1(83.52,85.72) v1(83.57,56.9) v1(83.57,1.02) v1(83.69,88.77) v1(83.72,82.55) v1(83.72,30.02) v1(83.72,28.12) v1(84.02,55.5) v1(84.23,43.31) v1(84.2,33.83) v1(84.28,37.64) v1(84.38,35.61) v1(84.84,64.85) v1(84.96,69.09) v1(85.72,80.14) v1(85.72,79.25) v1(85.72,77.47) v1(86.11,1.02) v1(86.23,88.77) v1(86.23,38.38) v1(86.21,3.86) v1(86.33,35.76) v1(86.36,50.8) v1(86.41,33.88) v1(86.46,29.95) v1(86.72,58.34) v1(86.94,60.27) v1(87.38,36.58) v1(87.76,50.8) v1(88.29,85.78) v1(88.37,67.61) v1(88.39,29.95) v1(88.49,82.6) v1(88.54,73.23) v1(88.52,43.18) v1(88.54,18.31) v1(88.65,77.6) v1(88.72,69.93) v1(88.77,88.77) v1(89.31,68.96) v1(89.36,56.69) v1(89.53,66.24) v1(89.66,62.87) v1(89.94,61.34) v1(90.3,77.6) v1(90.42,3.66) v1(90.63,67.34) v1(90.68,1.02) v1(91.31,88.77) v1(91.57,50.8) v1(91.92,59.72) v1(92.13,56.92) v1(92.53,30.2) v1(92.74,9.6) v1(92.84,50.8) v1(92.96,43.18) v1(92.96,23.83) v1(93.22,1.02) v1(93.73,85.75) v1(93.75,70.56) v1(93.85,88.77) v1(93.93,82.58) v1(93.9,37.21) v1(93.85,32.94) v1(94.11,67.23) v1(94.11,50.8) v1(94.36,65.28) v1(94.41,18.39) v1(94.97,72.64) v1(95.52,26.17) v1(95.76,81.03) v1(95.76,79.88) v1(95.76,78.74) v1(95.76,1.02) v1(95.94,68.07) v1(95.94,61.75) v1(96.06,56.57) v1(96.14,16.79) v1(96.27,14.86) v1(96.39,88.77) v1(96.39,8.08) v1(96.42,3.56) v1(96.52,12.95) v1(96.65,37.47) v1(96.71,27.12) v1(96.88,9.75) v1(97.1,70.48) v1(97.41,43.18) v1(97.49,65.05) v1(97.74,85.75) v1(97.94,82.58) v1(98.09,14.88) v1(98.3,12.83) v1(98.42,57.07) v1(98.53,36.93) v1(98.55,61.77) v1(98.81,1.02) v1(98.93,88.77) v1(98.88,28.7) v1(99.01,33.15) v1(99.11,11.68) v1(99.39,70.03) v1(99.39,12.73) v1(99.62,24.6) v1(99.65,22) v1(99.9,19.94) v1(100.71,79.88) v1(100.84,77.09) v1(101.35,1.02) v1(101.47,88.77) v1(101.5,61.37) v1(101.73,85.6) v1(101.8,12.73) v1(101.89,23.76) v1(102.36,13.84) v1(102.59,3.71) v1(102.74,82.55) v1(102.9,26.54) v1(102.9,22.12) v1(103.25,12.75) v1(103.4,45.9) v1(103.38,15.37) v1(103.45,65.02) v1(103.61,51.56) v1(103.89,58.17) v1(103.89,1.02) v1(104.01,88.77) v1(104.01,14.73) v1(104.14,61.72) v1(104.39,26.26) v1(104.9,56.24) v1(104.9,49.76) v1(104.9,38.35) v1(104.85,37.31) v1(104.85,24.59) v1(104.98,31.85) v1(105.03,8.56) v1(105.28,13.34) v1(105.54,77.6) v1(105.79,79.63) v1(105.79,11.81) v1(106.35,76.2) v1(106.32,16.71) v1(106.43,1.02) v1(106.53,65.91) v1(106.55,88.77) v1(106.63,68.25) v1(106.55,57.91) v1(106.55,53.75) v1(106.55,51.41) v1(106.55,38.46) v1(106.63,37.26) v1(106.63,31.85) v1(106.55,14.73) v1(106.93,81.03) v1(107.14,11.13) v1(107.9,78.36) v1(107.9,21.72) v1(108.97,77.28) v1(108.97,76.52) v1(108.97,75.76) v1(108.97,24.64) v1(108.97,1.02) v1(109.09,88.77) v1(109.22,12.45) v1(109.45,51.64) v1(109.47,3.33) v1(109.58,82.5) v1(109.63,63.98) v1(109.73,77.28) v1(109.73,76.52) v1(109.73,75.76) v1(109.93,36.65) v1(109.86,21.41) v1(110.41,13.39) v1(110.49,77.28) v1(110.49,76.52) v1(110.49,75.76) v1(110.49,69.57) v1(110.46,44.73) v1(110.49,23.6) v1(111.33,83.16) v1(111.33,81.74) v1(111.53,46.25) v1(111.51,36.75) v1(111.48,11.66) v1(111.51,1.02) v1(111.63,88.77) v1(111.71,78.36) v1(111.68,59.44) v1(112.06,38.81) v1(112.29,51.56) v1(112.27,21.08) v1(112.27,12.7) v1(112.42,24.59) v1(112.62,83.13) v1(112.75,36.75) v1(112.88,81.1) v1(112.95,44.73) v1(113.21,77.57) v1(113.41,63.3) v1(113.59,70.18) v1(113.59,22.35) v1(113.77,38.66) v1(114.05,42.16) v1(114.05,1.02) v1(114.07,66.34) v1(114.17,88.77) v1(114.17,51.56) v1(114.22,12.67) v1(114.68,24.13) v1(114.81,20.45) v1(114.81,14.63) v1(115.32,83.06) v1(115.32,80.9) v1(115.32,78.49) v1(115.32,76.07) v1(115.44,38.71) v1(115.44,11.56) v1(115.82,34.42) v1(115.82,33.78) v1(115.82,26.16) v1(115.82,25.4) v1(115.98,26.82) v1(116.33,42.42) v1(116.33,41.78) v1(116.54,27.64) v1(116.59,34.04) v1(116.59,1.02) v1(116.71,88.77) v1(117.14,59.99) v1(117.09,42.29) v1(117.22,46.61) v1(117.2,12.83) v1(117.47,27.56) v1(117.53,15.34) v1(117.55,24.03) v1(117.58,17.55) v1(117.7,11.53) v1(117.83,19.63) v1(117.86,42.29) v1(117.91,39.04) v1(118.97,67.84) v1(119.13,1.02) v1(119.18,70.18) v1(119.25,88.77) v1(119.25,23.47) v1(119.25,18.41) v1(119.28,14.33) v1(119.41,16.46) v1(119.76,83.19) v1(119.76,81.41) v1(119.89,79.5) v1(119.94,37.44) v1(121.41,83.31) v1(121.56,78.41) v1(121.67,1.02) v1(121.79,88.77) v1(122,60.12) v1(122.1,68.68) v1(122.17,51.69) v1(122.43,77.28) v1(122.43,76.52) v1(122.43,75.76) v1(122.5,5.99) v1(123.04,22.15) v1(122.96,17.12) v1(123.04,11.05) v1(123.19,77.28) v1(123.19,76.52) v1(123.19,75.76) v1(123.27,66.17) v1(123.7,83.19) v1(123.77,62.97) v1(123.95,77.28) v1(123.95,76.52) v1(123.95,75.76) v1(124.21,1.02) v1(124.33,88.77) v1(125.02,70.18) v1(125.22,83.06) v1(125.35,2.92) v1(125.48,81.66) v1(125.6,79.76) v1(125.98,15.19) v1(126.19,17.73) v1(126.75,1.02) v1(126.87,88.77) v1(126.89,36.83) v1(127.46,25.15) v1(127.99,60.1) v1(128.14,70.18) v1(128.68,23.22) v1(129.06,14.91) v1(129.06,11.94) v1(129.29,1.02) v1(129.41,88.77) v1(129.39,20.62) v1(129.59,65.61) v1(129.9,49.61) v1(130.15,35.17) v1(130.3,28.19) v1(130.33,25.1) v1(130.61,82.7) v1(130.66,68.55) v1(130.84,78) v1(130.84,62.1) v1(130.91,72.87) v1(130.94,28.83) v1(130.94,28.19) v1(131.04,23.7) v1(131.09,18.31) v1(131.32,8.89) v1(131.44,21.13) v1(131.6,36.5) v1(131.57,28.83) v1(131.57,28.19) v1(131.62,15.47) v1(131.6,13.06) v1(131.83,1.02) v1(132.28,29.01) v1(132.42,38.31) v1(132.92,49.78) v1(133.81,38.2) v1(133.93,36.28) v1(133.99,27.81) v1(133.99,27.18) v1(133.99,26.42) v1(134.11,59.87) v1(134.14,48.44) v1(134.08,41.04) v1(134.16,39.44) v1(134.24,10.54) v1(134.29,21.08) v1(134.37,5.71) v1(134.37,1.02) v1(134.49,88.77) v1(135.1,16.51) v1(135.23,19.02) v1(135.33,82.73) v1(135.38,68.58) v1(135.56,78.03) v1(135.64,72.9) v1(135.97,36.47) v1(136.12,48.46) v1(136.1,38.39) v1(136.3,50.06) v1(136.8,10.72) v1(136.78,8) v1(136.91,25.27) v1(136.91,24.64) v1(136.91,15.06) v1(136.91,1.02) v1(137.03,88.77) v1(137.01,29.39) v1(137.16,32.31) v1(137.29,4.27) v1(137.54,25.27) v1(137.54,24.64) v1(137.68,38.47) v1(138.18,24.64) v1(138.48,62.18) v1(138.48,48.77) v1(138.53,35.33) v1(138.71,21.84) v1(138.81,24.64) v1(138.99,33.07) v1(139.09,29.64) v1(139.37,13.77) v1(139.45,1.02) v1(139.57,88.77) v1(139.95,10.72) v1(140.13,51.23) v1(140.44,37.16) v1(140.46,82.68) v1(140.51,68.53) v1(140.61,54.66) v1(140.64,40.79) v1(140.69,77.98) v1(140.77,72.85) v1(141.05,4.55) v1(141.22,22.28) v1(141.4,38.79) v1(141.81,11.61) v1(141.96,48.34) v1(141.99,1.02) v1(142.75,43.08) v1(142.8,56.21) v1(143.15,28.09) v1(143.38,53.52) v1(143.43,30.63) v1(143.43,10.72) v1(143.69,49.38) v1(144.53,1.02) v1(144.55,41.15) v1(144.65,88.77) v1(144.7,43.81) v1(144.83,27.25) v1(144.91,30.38) v1(144.98,4.37) v1(145.06,37.8) v1(145.21,51.26) v1(145.34,9.09) v1(145.41,82.68) v1(145.64,77.98) v1(146.61,48.29) v1(146.56,28.88) v1(146.79,30.15) v1(146.94,6.22) v1(146.99,42.49) v1(147.07,1.02) v1(147.19,88.77) v1(147.42,64.29) v1(147.55,62.03) v1(147.73,57.35) v1(147.78,51.44) v1(148.13,69.32) v1(148.11,58.62) v1(148.11,56.03) v1(148.11,54.03) v1(148.21,71.86) v1(148.39,73.96) v1(148.59,67.51) v1(148.67,66.27) v1(148.74,43.84) v1(148.79,64.87) v1(149.2,61.87) v1(149.25,48.84) v1(149.53,82.22) v1(149.61,1.02) v1(149.73,88.77) v1(149.81,29.82) v1(149.89,9.22) v1(150.09,4.01) v1(150.16,6.58) v1(150.55,71.78) v1(150.5,66.85) v1(150.6,69.22) v1(150.67,37.31) v1(151.16,50.9) v1(151.26,59.05) v1(151.49,61.75) v1(151.59,63.93) v1(151.69,43.87) v1(151.94,4.39) v1(152.15,1.02) v1(152.2,7.65) v1(152.27,88.77) v1(152.37,10.08) v1(152.48,78.74) v1(153.21,83.85) v1(154.08,46.13) v1(154.43,29.46) v1(155.09,42.75) v1(155.12,8.31) v1(156.18,45.8) v1(156.26,49.45) v1(156.51,41.25) v1(156.46,38.13) v1(156.49,31.85) v1(156.64,20.07) v1(156.57,16.56) v1(156.77,26.9) v1(156.77,23.03) v1(157.3,81.23) v1(157.35,14) v1(157.61,71.12) v1(157.56,56.67) v1(157.66,77.37) v1(157.68,63.47) v1(157.68,51.59) v1(159,83.19) v1(159,80.64) v1(159,78.11) v1(159,75.56) v1(159,73.03) v1(159,70.48) v1(159,67.94) v1(159,65.41) v1(159,62.87) v1(159,60.33) v1(159,57.78) v1(159,55.24) v1(159,52.7) v1(159,50.16) v1(159,47.62) v1(159,45.09) v1(159,42.55) v1(159,40.01) v1(159,37.47) v1(159,34.92) v1(159,32.38) v1(159,29.84) v1(159,27.3) v1(159,24.77) v1(159,22.23) v1(159,19.68) v1(159,17.14) v1(159,14.61) v1(159,12.06) v1(159,9.53) v1(159,6.99)
VBUS:
  vias: v1(93.83,77.75) v1(93.84,77.15) v1(94.44,77.75) v1(94.44,77.14)
AC_MICBIAS: length 8.4
  TOP w0.178: U14.18 52.46,38.75 50.67,36.96 v1(50.67,36.7)
  BOTTOM w0.305: R107.2 48.39,35.18 48.77,35.56 C135.1 C114.1 50.67,35.94 v1(50.67,36.7)
AC_MICIP: length 29.3
  BOTTOM w0.201: JP17.2 41.91,25.78 41.91,32.18 45.8,36.07 46.48,36.07 C56.2
AC_OUTL: length 37.4
  TOP w0.201: U14.15 51.35,39.8 50.48,38.92 50.48,38.92 50.23,38.67 50.23,38.67 50.04,38.48 49.79,38.48 v1(49.78,38.48)
  BOTTOM w0.201: JP23.2 35.38,17.48 36.14,17.48 39.12,20.45 39.12,32 44.7,37.59 46.86,37.59 47.62,38.35 49.66,38.35 v1(49.78,38.48)
AMP+: length 4.7
  BOTTOM w0.508: R98.2 26.16,10.67 25.65,10.16 U13.5 R94.1
AMP-: length 2
  BOTTOM w0.508: U13.8 R90.1
ARM_DBGRQ: length 3.4
  BOTTOM w0.102: R142.1 U18.17
ARM_JTAG_TCK: length 41.4
  TOP w0.102: U18.9 147.57,65.53 146.18,64.14 116.59,64.14 JP9.3
  BOTTOM w0.102: R138.1 U18.9
ARM_JTAG_TDI: length 43.6
  TOP w0.102: U18.5 151.51,69.34 151.51,64.9 150.75,64.14 148.72,64.14 148.08,63.5 121.03,63.5 JP7.3
  BOTTOM w0.102: R136.1 U18.5
ARM_JTAG_TDO: length 31.1
  TOP w0.102: U18.13 146.3,60.45 144.02,62.74 125.35,62.74 JP12.3
  BOTTOM w0.102: R140.1 U18.13
ARM_JTAG_TMS: length 47.6
  TOP w0.102: JP10.3 112.14,64.77 142.21,64.77 144.5,67.06 149.22,67.06 U18.7
  BOTTOM w0.102: R137.1 U18.7
ARM_JTAG_TRSTN: length 52.6
  TOP w0.102: U18.3 151.51,71.88 154.2,71.88 154.31,71.78 154.31,57.15 153.92,56.77 146.81,56.77 146.18,56.13 v1(145.8,56.13) 145.54,56.39 145.54,58.8 142.75,61.59 129.29,61.59 JP11.3
  BOTTOM w0.102: R135.1 U18.3 ; R143.1 v1(145.8,56.13)
BOOT_MODE: length 43.1
  TOP w0.102: v1(56.67,47.88) 58.01,47.88 58.6,47.3 U14.77
  BOTTOM w0.102: JP1.2 22.48,50.8 42.65,50.8 46.33,47.12 51.38,47.12 52.12,46.38 55.17,46.38 v1(56.67,47.88)
BOOT_SEL0: length 28.5
  TOP w0.102: U14.75 59.3,47.69 57.89,49.1 v1(56.52,49.1)
  BOTTOM w0.102: v1(56.52,49.1) 56.52,49.07 54.46,47.02 52.38,47.02 51.65,47.75 46.59,47.75 42.81,51.54 37.74,51.54 JP3.2
BOOT_SEL1: length 35.8
  TOP w0.102: U14.76 58.95,47.46 57.91,48.49 v1(56.57,48.49)
  BOTTOM w0.102: v1(56.57,48.49) 56.34,48.49 54.53,46.69 52.25,46.69 51.51,47.42 46.46,47.42 42.72,51.16 30.12,51.16 JP2.2
CDS1: length 3.4
  BOTTOM w0.381: R129.2 JP29.2
CDS2: length 6.1
  BOTTOM w0.102: 8,78.74 12.83,78.74 JP30.2
CH_UART1_RX: length 41.1
  TOP w0.102: JP22.2 85.06,24.16 85.06,37.86 79.74,43.18 v1(79.53,43.18) ; v1(72.52,43.56) 70.85,41.9 U14.58
  BOTTOM w0.102: v1(79.53,43.18) 79.15,43.56 v1(72.52,43.56)
CIS_CLK: length 48
  TOP w0.102: v1(9.58,53.31) 8.05,54.84 J3.40
  BOTTOM w0.102: v1(9.58,53.31) 9.68,53.31 11.58,51.41 13.97,49.02 42.16,49.02 45.85,45.34 C52.2 R33.1
CIS_RSTN: length 54.9
  TOP w0.102: U14.8 52.32,42.25 52.03,42.55 51.56,42.55 51.41,42.7 48.79,42.7 47.35,41.25 v1(46.43,41.25) ; J3.14 v1(7.43,41.84)
  BOTTOM w0.102: v1(46.43,41.25) 46.2,41.02 37.52,41.02 31.78,35.28 13.99,35.28 v1(7.43,41.84)
